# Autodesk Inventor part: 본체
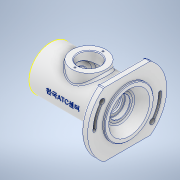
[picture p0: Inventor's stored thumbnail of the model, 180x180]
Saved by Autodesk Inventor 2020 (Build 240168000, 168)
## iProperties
Created: 2022-05
Part Number: 본체
Material: 알루미늄 6061
Document SubType Name: Modeling
Designer: Student
Density: 2.7 g/cm^3
Appearance: 알루미늄 - 평지
Mass: 686.756 g
Surface Area: 622.555 cm^2
Volume: 254.354 cm^3
Author: Student
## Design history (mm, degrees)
sketch "스케치1"
  geometry: L1 (-29.488, 0)-(29.488, 0); L2 (-56, 22.5)-(-48, 22.5); L3 (-45, 22.5)-(-45, 24); L4 (-45, 24)-(-48, 24); L5 (-48, 24)-(-48, 22.5); L6 (-45, 22.5)-(-34, 22.5); L7 (-34, 22.5)-(-34, 17.5); L8 (-34, 17.5)-(-31.75, 17.5); L9 (-31.75, 17.5)-(-31.75, 18.5); L10 (-31.75, 18.5)-(-30, 18.5); L11 (-30, 18.5)-(-30, 17.5); L12 (-30, 17.5)-(-19, 17.5); L13 (-19, 17.5)-(-19, 27); L14 (-19, 27)-(19, 27); L15 (19, 27)-(19, 17.5); L16 (19, 17.5)-(30, 17.5); L17 (30, 17.5)-(30, 15); L18 (30, 15)-(35, 15); L19 (35, 15)-(35, 11); L20 (35, 11)-(37.7, 11); L21 (37.7, 11)-(37.7, 15); L22 (37.7, 15)-(39.647, 15); L23 (59, 30)-(59, 36); L24 (59, 36)-(56, 36); L25 (56, 36)-(56, 58); L26 (56, 58)-(46, 58); L27 (46, 58)-(46, 32); L28 (46, 32)-(37.28, 32); L29 (37.28, 32)-(-56, 32); L30 (-56, 32)-(-56, 22.5); L31 (39.647, 15)-(45, 15); L32 (45, 15)-(45, 20); L33 (45, 20)-(59, 30); 2 further points
  constraints: 66 end point, 24 perpendicular, 4 horizontal, 4 point on line, 1 coincident, 1 midpoint, 1 parallel, 1 vertical
  dimensions: "d2" = 48 diameter of L4 L1; "d3" = 64 diameter of L29 L1; "d4" = 45 diameter of L6 L1; "d5" = 35 diameter of L8 L1; "d6" = 54 diameter of L14 L1; "d8" = 30 diameter of L18 L1; "d9" = 22 diameter of L20 L1; "d10" = 30 diameter of L22 L1; "d11" = 40 diameter of L32.end L1; "d12" = 60 diameter of L23.start L1; "d13" = 72 diameter of L23.end L1; "d14" = 116 diameter of L26 L1; "d18" = 11 distance between parallel lines of L13 L11; "d19" = 38 distance between parallel lines of L15 L13; "d20" = 1.75 distance of L9.end L10.end; "d21" = 4 distance between parallel lines of L11 L7; "d22" = 37 diameter of L10 L1; "d23" = 115 distance between parallel lines of L23 L30; "d24" = 8 distance between parallel lines of L30 L5; "d25" = 45 diameter of L2 L1; "d26" = 3 distance of L3.end L4.end; "d27" = 22 distance between parallel lines of L30 L7; "d28" = 11 distance of L15.end L16.end; "d29" = 5 distance of L17.end L18.end; "d30" = 14 horizontal distance of L32.end L23.start; "d31" = 7.3 distance of L31.end L21.end; "d32" = 56 distance from line of point (0, 0) L30; "d33" = 102 distance between parallel lines of L30 L27; "d34" = 3 distance of L23.end L24.end; "d38" = 19.35308 distance from line of L22.end L23; "d39" = 21.71953 distance from line of L28.end L23; "d40" = 29.51167 distance from line of L1.end L23
revolve "회전1" sketch "스케치1" stored, may be unused: angle "d35" = 90 deg
sketch "스케치2"
  geometry: L1 (-33.985, 47)-(33.985, 47); L2 (-33.985, -47)-(33.985, -47); C1 r 58 at (0, 0) reference; C2 r 36 at (0, 0) reference; A1 r 58 centre (0, 0) between (-33.985, 47) and (33.985, 47) reference; 5 further points
  constraints: 4 end point, 4 point on circle, 1 horizontal, 1 parallel
  dimensions: "d36" = 47 distance from line of L2 point (0, 0); "d37" = 94 distance between parallel lines of L2 L1
extrude "돌출1" cut sketch "스케치2" distance "d41" = 10; taper "d42" = 0 deg
node "작업 평면1"
sketch "스케치7"
  geometry: C1 r 25 at (0, 0); 1 further point
  constraints: 1 centre point, 1 coincident
  dimensions: "d67" = 25 radius of C1
extrude "돌출5" join sketch "스케치7" stored distance "d68" = 38; taper "d69" = 0 deg
sketch "스케치8"
  geometry: C1 r 25 at (0, 0) reference; C2 r 16 at (0, 0); 1 further point
  constraints: 1 centre point, 1 coincident
  dimensions: "d70" = 16 radius of C2
extrude "돌출6" cut sketch "스케치8" stored distance "d71" = 10; taper "d72" = 0 deg
sketch "스케치10"
  geometry: 2 further points
  constraints: 1 vertical alignment
  dimensions: "d80" = 20.5 distance of point (0, 20.5) point (0, 0)
hole "구멍2" sketch "스케치10" at (0, 20.5) diameter "d81" = 2.459; stored, may be unused: countersink angle "d85" = 90 deg, drill point angle "d87" = 118 deg; dims "d82" = 6, "d83" = 4, "d84" = 2, "d86" = 8
node "작업 평면2"
sketch "스케치11"
  geometry: L1 (56, -47)-(56, 47) reference; 2 further points
  constraints: 1 horizontal alignment, 1 other
  dimensions: "d92" = 62 distance from line of L1 point (-6, 0)
feature "엠보싱1" sketch "스케치11" dims "d2" = 48, "d3" = 64, "d4" = 45, "d5" = 35, "d6" = 54, "d8" = 30, "d9" = 22, "d10" = 30, "d11" = 40, "d12" = 60, "d13" = 72, "d14" = 116, "d18" = 11, "d19" = 38, "d20" = 1.75, "d21" = 4, "d22" = 37, "d23" = 115, "d24" = 8, "d25" = 45, "d26" = 3, "d27" = 22, "d28" = 11, "d29" = 5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
fillet "모깎기1" dims "d95" = 3
chamfer "모따기1" distance "d96" = 1; stored, may be unused: second distance "d97" = 2, angle "d98" = 45 deg
fillet "모깎기2" dims "d99" = 0.6
chamfer "모따기2" distance "d100" = 0.7; stored, may be unused: second distance "d101" = 2, angle "d102" = 30 deg
chamfer "모따기3" distance "d103" = 1; stored, may be unused: second distance "d104" = 2, angle "d105" = 30 deg
fillet "모깎기3" dims "d106" = 3
sketch "스케치12"
  geometry: C1 r 32 at (0, 0) reference; C2 r 22.5 at (0, 0) reference; 1 further point
fillet "모깎기4" dims "d107" = 3
fillet "모깎기5" dims "d120" = 3
chamfer "모따기4" distance "d121" = 1; stored, may be unused: second distance "d122" = 2, angle "d123" = 30 deg
chamfer "모따기5" distance "d124" = 1; stored, may be unused: second distance "d125" = 2, angle "d126" = 30 deg
feature "스레드1" dims "d127" = 8, "d128" = 0
sketch "스케치15"
  geometry: L1 (33, -44)-(81, -44); L2 (33, -44)-(69.77, -13.146); L3 (33, -44)-(-15, -44); L4 (33, -44)-(-3.77, -74.854); A1 r 48 centre (33, -44) between (81, -44) and (69.77, -13.146); A2 r 48 centre (33, -44) between (81, -44) and (69.77, -13.146); A3 r 50.25 centre (33, -44) between (83.25, -44) and (73.58, -14.364); A4 r 45.75 centre (33, -44) between (78.75, -44) and (70.033, -17.138); A5 r 2.25 centre (81, -44) between (78.75, -44) and (83.25, -44); A6 r 4 centre (69.77, -13.146) between (70.033, -17.138) and (73.58, -14.364); A7 r 48 centre (33, -44) between (-15, -44) and (-3.77, -74.854); A8 r 4 centre (-3.77, -74.854) between (-4.033, -70.862) and (-7.58, -73.636); A9 r 48 centre (33, -44) between (-15, -44) and (-3.77, -74.854); A10 r 50.25 centre (33, -44) between (-17.25, -44) and (-7.58, -73.636); A11 r 45.75 centre (33, -44) between (-12.75, -44) and (-4.033, -70.862); A12 r 2.25 centre (-15, -44) between (-12.75, -44) and (-17.25, -44); 1 further point
  constraints: 26 point on circle, 12 centre point, 8 end point, 4 tangent, 3 coincident, 2 horizontal, 1 concentric
  dimensions: "d131" = 48 radius of A1; "d132" = 40 deg angle of L1 L2; "d133" = 48 radius of A2; "d134" = 2.25 radius of A5; "d135" = 4 radius of A6; "d136" = 40 deg angle of L3 L4; "d138" = 4 radius of A8; "d142" = 48 radius of A9; "d143" = 2.25 radius of A12
extrude "돌출10" cut sketch "스케치15" distance "d144" = 10; taper "d145" = 0 deg
extrude "돌출11" cut sketch "스케치15" extent not by distance; stored distance "d146" = 4.4; taper "d147" = 0 deg
sketch "스케치16"
  geometry: A1 r 2.25 centre (81, -44) between (78.75, -44) and (83.25, -44) reference; A2 r 50.25 centre (33, -44) between (83.25, -44) and (73.58, -14.364) reference; A3 r 45.75 centre (33, -44) between (78.75, -44) and (70.033, -17.138) reference; A4 r 4 centre (69.77, -13.146) between (73.58, -14.364) and (70.033, -17.138) reference; A5 r 48 centre (33, -44) between (81, -44) and (69.77, -13.146); A6 r 52 centre (33, -44) between (85, -44) and (72.834, -10.575); A7 r 44 centre (33, -44) between (77, -44) and (66.706, -15.717); A8 r 4 centre (81, -44) between (77, -44) and (85, -44); A9 r 4 centre (69.77, -13.146) between (72.834, -10.575) and (66.706, -15.717); 3 further points
  constraints: 10 point on circle, 5 centre point, 4 tangent, 1 coincident, 1 concentric
extrude "돌출12" cut sketch "스케치16" distance "d148" = 4.4; taper "d149" = 0 deg
node "솔리드1"
pattern_circular "원형 패턴1" dims angle "d89" = 360 deg
pattern_circular "원형 패턴2" dims angle "d151" = 360 deg
node "투영된 루프1"
feature "A9D066F2-1C7D-4E18-AEED-F7BC21143FA4" dims "d81" = 2.459, "d82" = 6, "d83" = 4, "d84" = 2, "d85" = 90 deg, "d86" = 8, "d87" = 118 deg
other parameters: "d66" = 38, "d91" = 32
